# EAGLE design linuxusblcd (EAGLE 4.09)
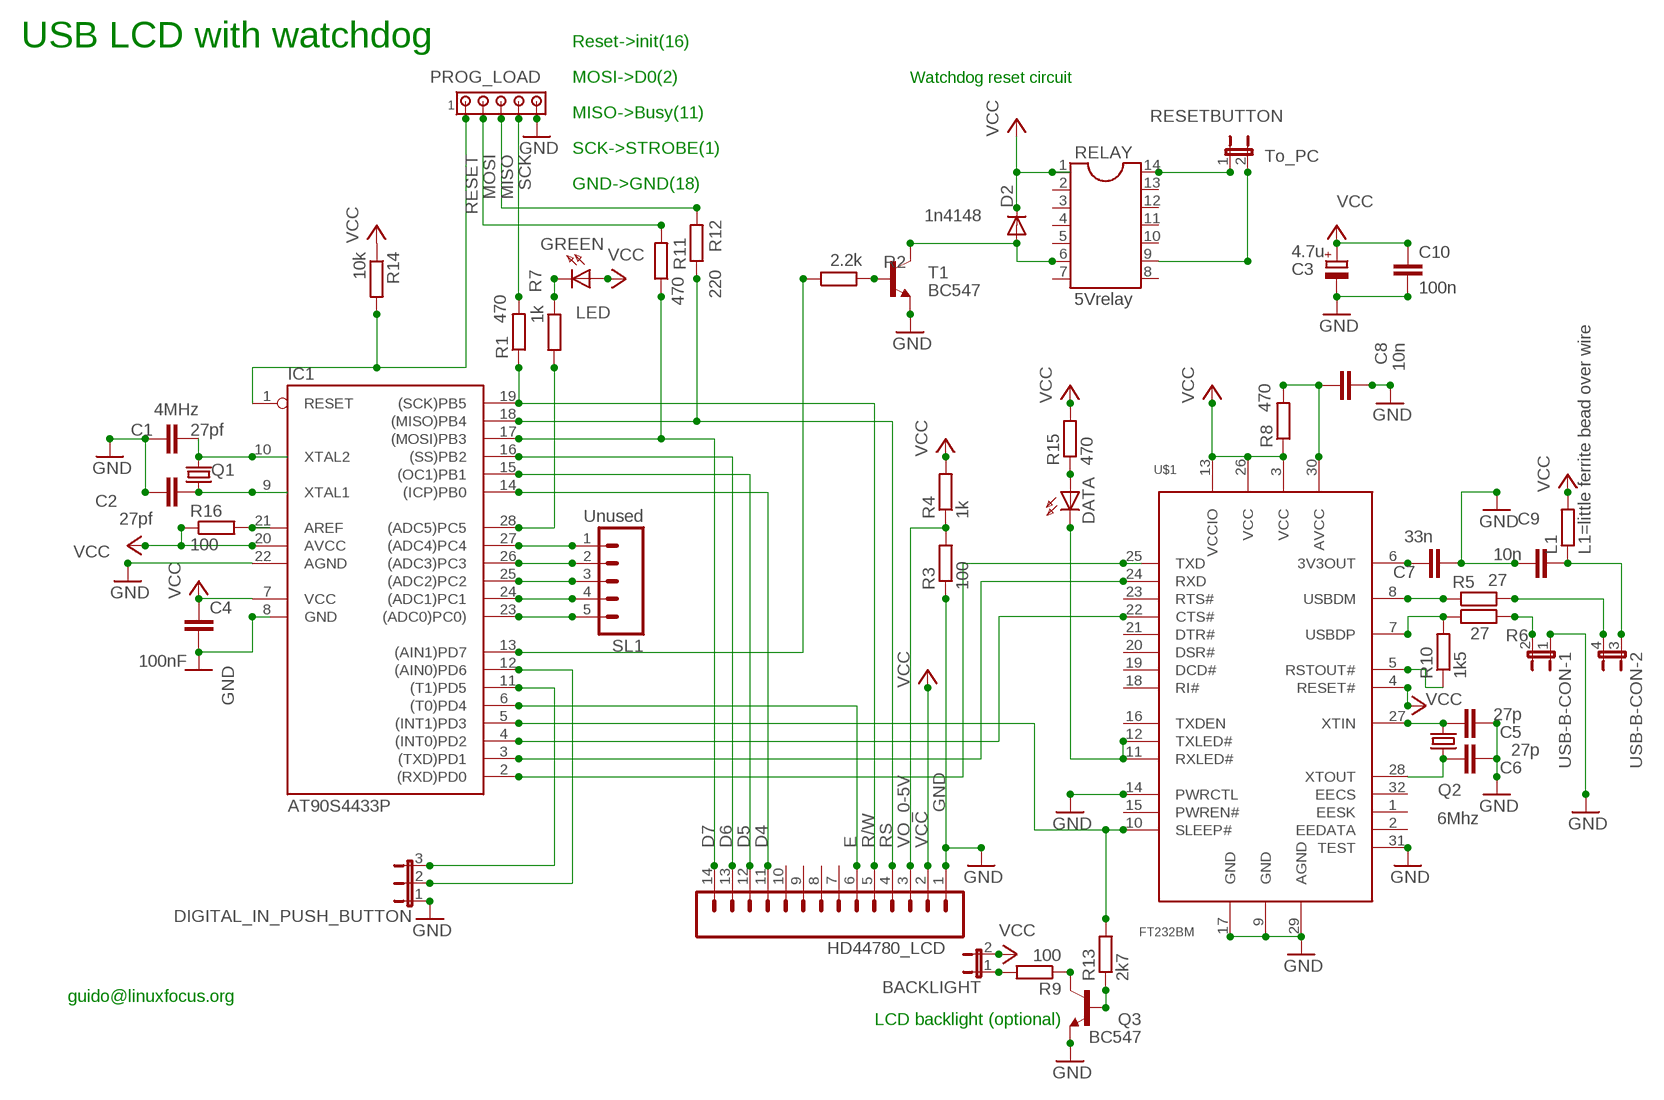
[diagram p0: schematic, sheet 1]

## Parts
BACKLIGHT  JP1E  [JP1]
C1  27pf  C2.5/2  [C2.5-2]
C2  27pf  C2.5/2  [C2.5-2]
C3  4.7u  CPOL-EUE2.5-7  [E2,5-7]
C4  100nF  C-EU025-040X050  [C025-040X050]
C5  27p  C2.5/2  [C2.5-2]
C6  27p  C2.5/2  [C2.5-2]
C7  33n  C-EU050-025X075  [C050-025X075]
C8  10n  C-EU025-030X050  [C025-030X050]
C9  10n  C-EU025-030X050  [C025-030X050]
C10  100n  C-EU025-030X050  [C025-030X050]
D2  1n4148  DIODE-D-5  [D-5]
DATA  LED5MM  [LED5MM]
DIGITAL_IN_PUSH_BUTTON  JP2E  [JP2]
GREEN  LED  LED3MM  [LED3MM]
HD44780_LCD  M14  [14P]
IC1  AT90S4433P  [DIL28-3]
L1  L1=little ferrite bead over wire  R-EU_0204/5  [0204/5]
PROG_LOAD  MTA05-100  [10X05MTA]
Q1  4MHz  HC49U-V  [HC49U-V]
Q2  6Mhz  CRYTALHC49U-V  [HC49U-V]
Q3  BC547  [TO92]
R1  470  R-EU_0204/7  [0204/7]
R2  2.2k  R-EU_0204/5  [0204/5]
R3  100  R-EU_0204/7  [0204/7]
R4  1k  R-EU_0204/7  [0204/7]
R5  27  R-EU_0204/5  [0204/5]
R6  27  R-EU_0204/5  [0204/5]
R7  1k  R-EU_0204/7  [0204/7]
R8  470  R-EU_0204/5  [0204/5]
R9  100  R-EU_0204/7  [0204/7]
R10  1k5  R-EU_0204/5  [0204/5]
R11  470  R-EU_0204/7  [0204/7]
R12  220  R-EU_0204/7  [0204/7]
R13  2k7  R-EU_0204/7  [0204/7]
R14  10k  R-EU_0204/7  [0204/7]
R15  470  R-EU_0204/7  [0204/7]
R16  100  R-EU_0204/7  [0204/7]
RELAY  5Vrelay  DIL14  [DIL14]
RESETBUTTON  To_PC  JP1E  [JP1]
SL1  Unused  M05  [05P]
T1  BC547  [TO92]
U$1  FT232BM  [TQFP32-08]
USB-B-CON  JP2QE  [JP2Q]

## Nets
3V3OUT: C7.1 U$1.6(3V3OUT)
AREF: IC1.21(AREF) R16.2
AVCC: C8.2 R8.2 U$1.30(AVCC)
D4: HD44780_LCD.11 IC1.14((ICP)PB0)
D5: HD44780_LCD.12 IC1.15((OC1)PB1)
D6: HD44780_LCD.13 IC1.16((SS)PB2)
D7: HD44780_LCD.14 IC1.17((MOSI)PB3) R11.1
E: HD44780_LCD.6 IC1.6((T0)PD4)
GND: C1.1 C2.1 C3.- C4.2 C5.2 C6.2 C7.2 C8.1 C9.1 C10.2 DIGITAL_IN_PUSH_BUTTON.1 HD44780_LCD.1 IC1.8(GND) IC1.22(AGND) PROG_LOAD.5 Q3.1(E) R3.1 T1.1(E) U$1.9(GND) U$1.14(PWRCTL) U$1.17(GND) U$1.29(AGND) U$1.31(TEST) USB-B-CON.1
MISO: PROG_LOAD.3 R12.2
MOSI: PROG_LOAD.2 R11.2
N$1: IC1.4((INT0)PD2) U$1.22(CTS#)
N$2: C2.2 IC1.9(XTAL1) Q1.1
N$3: C5.1 Q2.2 U$1.27(XTIN)
N$4: R2.2 T1.2(B)
N$5: IC1.28((ADC5)PC5) R7.2
N$6: DIGITAL_IN_PUSH_BUTTON.3 IC1.11((T1)PD5)
N$7: GREEN.K(C) R7.1
N$8: RELAY.9 RESETBUTTON.2
N$9: RELAY.14 RESETBUTTON.1
N$10: C6.1 Q2.1 U$1.28(XTOUT)
N$11: R5.2 USB-B-CON.4
N$12: R6.2 USB-B-CON.2
N$14: IC1.13((AIN1)PD7) R2.1
N$16: R5.1 U$1.8(USBDM)
N$17: DATA.A R15.1
N$18: IC1.27((ADC4)PC4) SL1.1
N$20: R6.1 R10.2 U$1.7(USBDP)
N$21: DATA.K(C) U$1.11(RXLED#) U$1.12(TXLED#)
N$22: C9.2 L1.1 USB-B-CON.3
N$23: R10.1 U$1.5(RSTOUT#)
N$24: IC1.5((INT1)PD3) R13.2 U$1.10(SLEEP#)
N$25: IC1.26((ADC3)PC3) SL1.2
N$26: IC1.25((ADC2)PC2) SL1.3
N$27: IC1.24((ADC1)PC1) SL1.4
N$28: IC1.23((ADC0)PC0)) SL1.5
N$30: DIGITAL_IN_PUSH_BUTTON.2 IC1.12((AIN0)PD6)
N$31: IC1.3((TXD)PD1) U$1.24(RXD)
N$32: BACKLIGHT.1 R9.2
N$33: Q3.3(C) R9.1
N$34: IC1.2((RXD)PD0) U$1.25(TXD)
N$35: Q3.2(B) R13.1
N$36: C1.2 IC1.10(XTAL2) Q1.2
R/W: HD44780_LCD.5 IC1.19((SCK)PB5) R1.1
RCTL: D2.A RELAY.6 T1.3(C)
RESET: IC1.1(RESET) PROG_LOAD.1 R14.2
RS: HD44780_LCD.4 IC1.18((MISO)PB4) R12.1
SCK: PROG_LOAD.4 R1.2
VCC: BACKLIGHT.2 C3.+ C4.1 C10.1 D2.C GREEN.A HD44780_LCD.2 IC1.7(VCC) IC1.20(AVCC) L1.2 R4.2 R8.1 R14.1 R15.2 R16.1 RELAY.1 U$1.3(VCC) U$1.4(RESET#) U$1.13(VCCIO) U$1.26(VCC)
VO_0-5V: HD44780_LCD.3 R3.2 R4.1
Unconnected: HD44780_LCD.7 HD44780_LCD.8 HD44780_LCD.9 HD44780_LCD.10 RELAY.2 RELAY.3 RELAY.4 RELAY.5 RELAY.7 RELAY.8 RELAY.10 RELAY.11 RELAY.12 RELAY.13 U$1.1(EESK) U$1.2(EEDATA) U$1.15(PWREN#) U$1.16(TXDEN) U$1.18(RI#) U$1.19(DCD#) U$1.20(DSR#) U$1.21(DTR#) U$1.23(RTS#) U$1.32(EECS)

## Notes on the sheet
- USB LCD with watchdog | Reset->init(16)
- MOSI->D0(2) | Watchdog reset circuit
- MISO->Busy(11)
- SCK->STROBE(1)
- GND->GND(18)
- guido@linuxfocus.org
- LCD backlight (optional)

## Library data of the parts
BACKLIGHT RESETBUTTON = jumper:JP1E: JUMPER
C1 C2 C5 C6 = capacitor-wima:C: CAPACITOR
C3 = rcl:CPOL-EU: POLARIZED CAPACITOR, European symbol
C4 C7-C10 = rcl:C-EU: CAPACITOR, European symbol
D2 = diode:DIODE-: DIODE
DATA = led:LED: LED
DIGITAL_IN_PUSH_BUTTON = jumper:JP2E: JUMPER
GREEN = led:LED3MM: LED
HD44780_LCD = con-amp-quick:M14: AMP QUICK CONNECTOR
IC1 = atmel:AT90S4433: MICROCONTROLLER 4 Kbytes FLASH 128 bytes SRAM 256 bytes EEPROM UART 6-channel 10 bit ADC
L1 R1-R3 R5-R16 = rcl:R-EU_: RESISTOR, European symbol
PROG_LOAD = con-amp:MTA05-100: AMP CONNECTOR
Q1 = crystal:HC49U-V: CRYSTAL
Q2 = crystal:CRYTAL: CRYSTAL
Q3 = transistor-npn:BC547*: NPN Transistor
R4 = rcl_gus:R-EU_: RESISTOR, European symbol
RELAY = dil:DIL14: SOCKET Dual In Line
SL1 = con-amp-quick:M05: AMP QUICK CONNECTOR
T1 = transistor-npn:BC547: NPN TRANSISTOR
U$1 = ftdi:FT232BM: USB-Seriell Converter USB 1.1 and USB 2.0
USB-B-CON = jumper:JP2QE: JUMPER

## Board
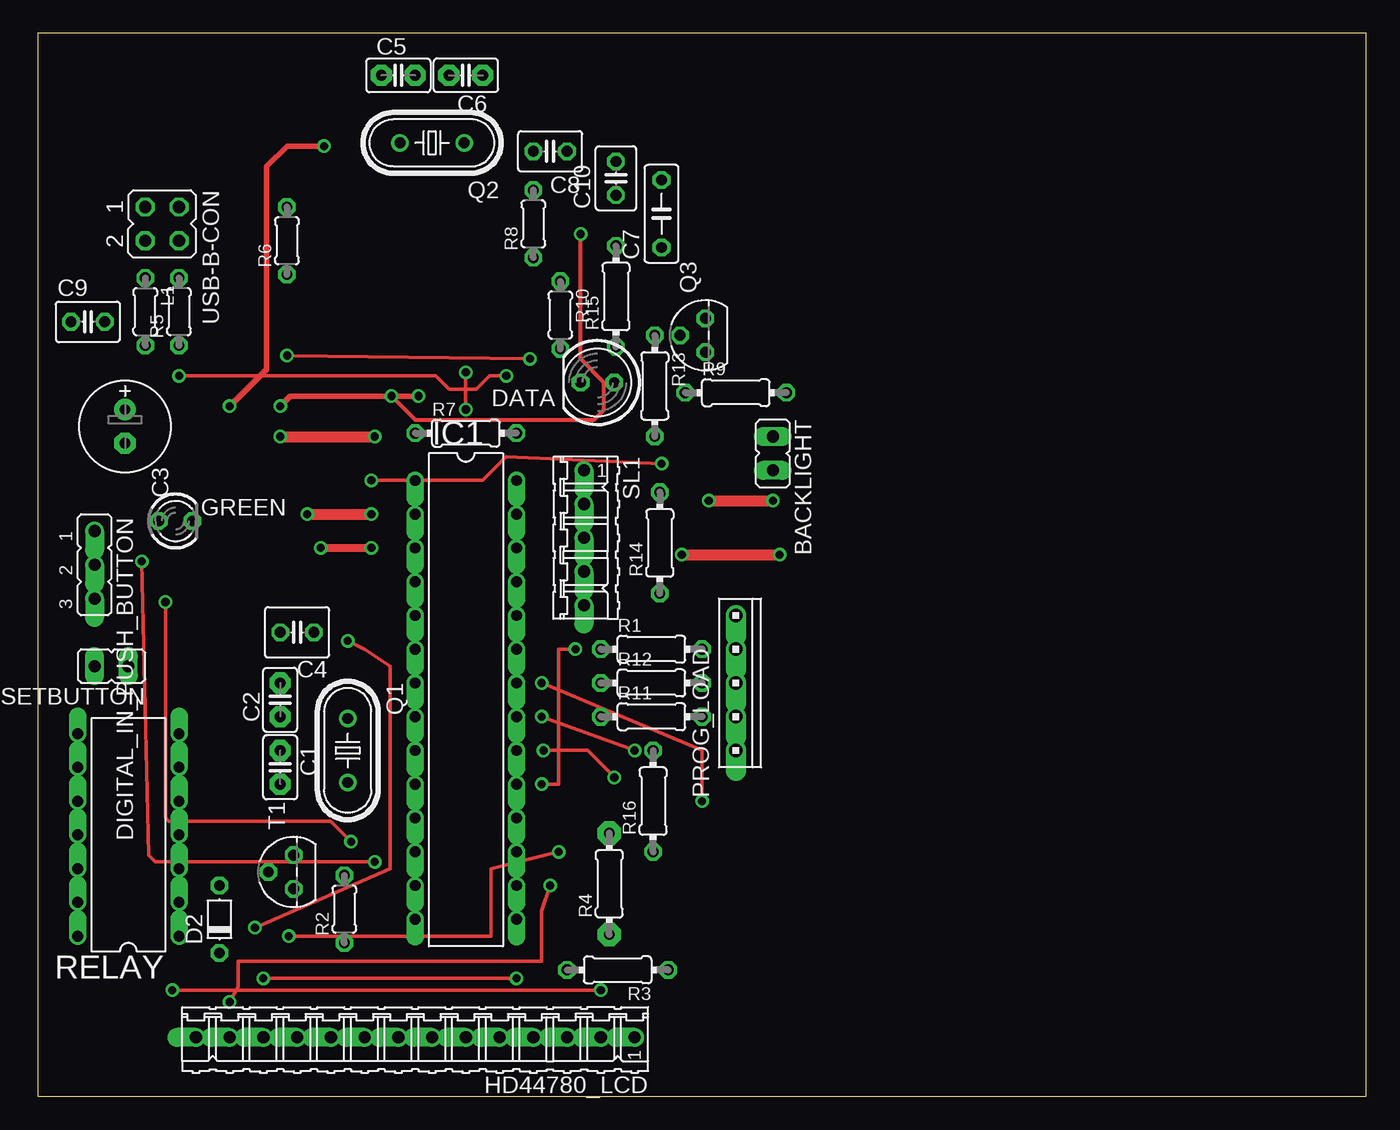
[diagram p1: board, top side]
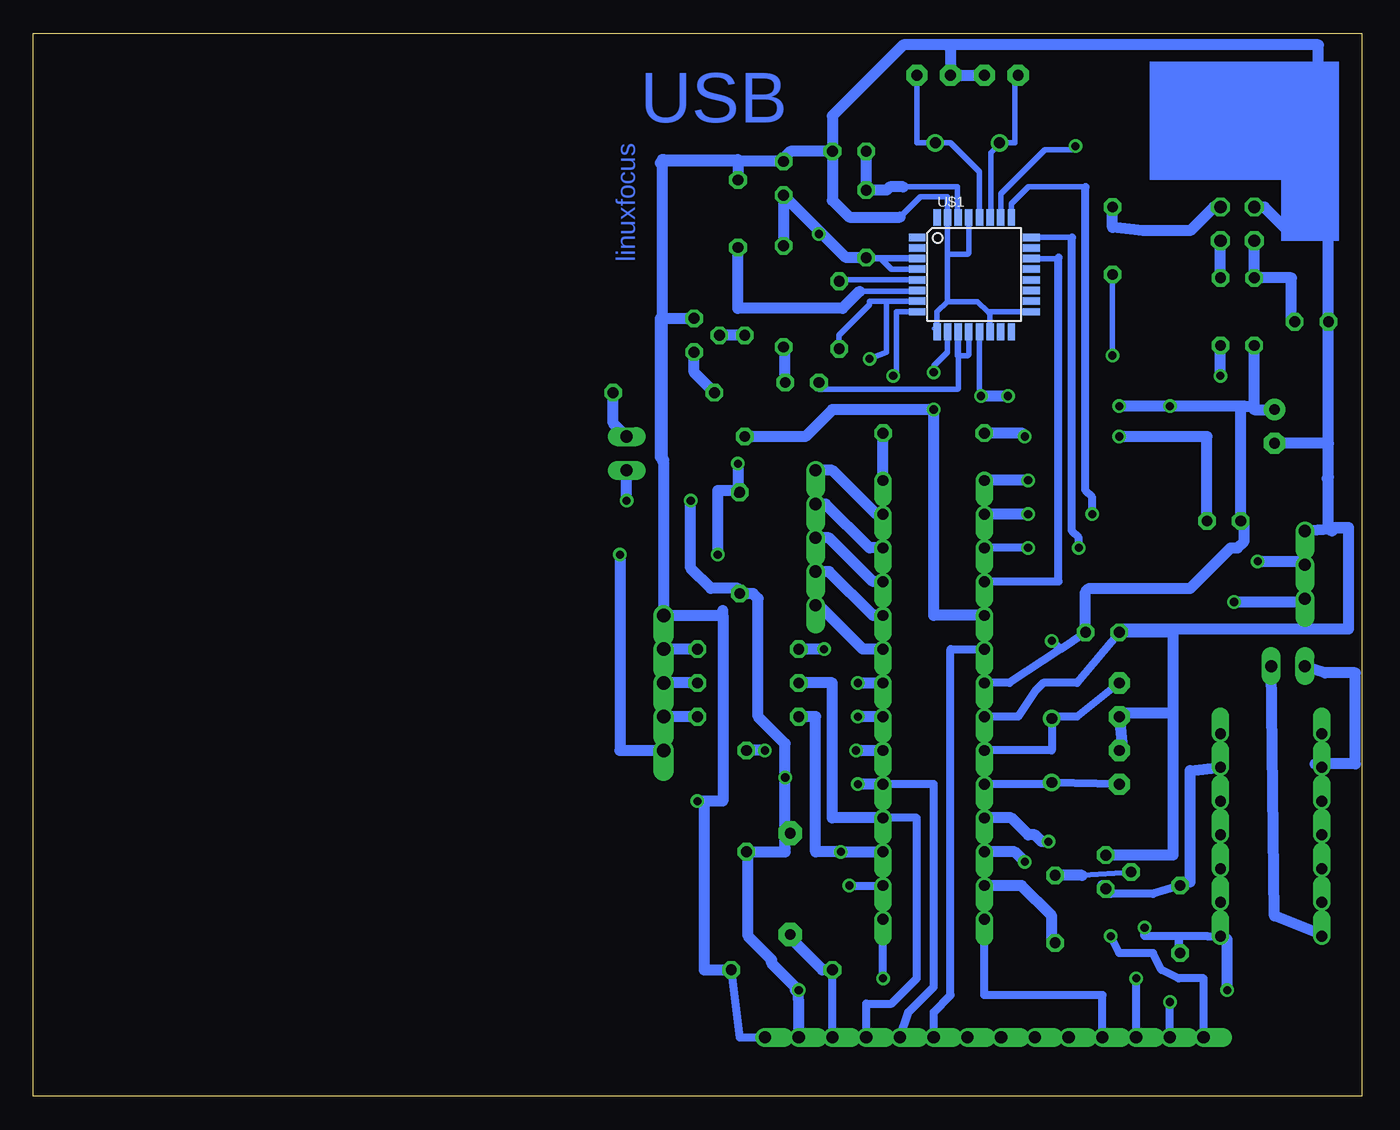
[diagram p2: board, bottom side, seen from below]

Size 100 x 80 mm. Coordinates in mm from the lower left corner, seen from the top.
Outline: 0,0 100,0 100,80 0,80 0,0
Copper layers used: Top, Bottom

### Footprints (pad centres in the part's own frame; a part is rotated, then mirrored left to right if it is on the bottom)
JP1 = drill 0.914 long: 1 0,-1.27; 2 0,1.27
C2.5-2 = drill 0.813 pad 1.6 octagon: 1 -1.27,0; 2 1.27,0
E2,5-7 = drill 0.813 pad 1.6 round: + -1.27,0 | drill 0.813 pad 1.6 octagon: - 1.27,0
C025-040X050 = drill 0.813 octagon: 1 -1.27,0; 2 1.27,0
C050-025X075 = drill 0.813 octagon: 1 -2.54,0; 2 2.54,0
C025-030X050 = drill 0.813 octagon: 1 -1.27,0; 2 1.27,0
D-5 = drill 0.813 octagon: A 2.54,0; C -2.54,0
LED5MM = drill 0.813 octagon: A -1.27,0; K 1.27,0
JP2 = drill 0.914 offset: 1 -2.54,0; 2 0,0; 3 2.54,0
LED3MM = drill 0.813 octagon: A -1.27,0; K 1.27,0
14P = drill 0.914 offset: 1 -16.51,0; 2 -13.97,0; 3 -11.43,0; 4 -8.89,0; 5 -6.35,0; 6 -3.81,0; 7 -1.27,0; 8 1.27,0; 9 3.81,0; 10 6.35,0; 11 8.89,0; 12 11.43,0; 13 13.97,0; 14 16.51,0
DIL28-3 = drill 0.813 offset: 1 -16.51,-3.81; 2 -13.97,-3.81; 3 -11.43,-3.81; 4 -8.89,-3.81; 5 -6.35,-3.81; 6 -3.81,-3.81; 7 -1.27,-3.81; 8 1.27,-3.81; 9 3.81,-3.81; 10 6.35,-3.81; 11 8.89,-3.81; 12 11.43,-3.81; 13 13.97,-3.81; 14 16.51,-3.81; 15 16.51,3.81; 16 13.97,3.81; 17 11.43,3.81; 18 8.89,3.81; 19 6.35,3.81; 20 3.81,3.81; 21 1.27,3.81; 22 -1.27,3.81; 23 -3.81,3.81; 24 -6.35,3.81; 25 -8.89,3.81; 26 -11.43,3.81; 27 -13.97,3.81; 28 -16.51,3.81
0204/5 = drill 0.813 octagon: 1 -2.54,0; 2 2.54,0
10X05MTA = drill 1.016 offset: 1 5.08,0; 2 2.54,0; 3 0,0; 4 -2.54,0; 5 -5.08,0
HC49U-V = drill 0.813 round: 1 -2.413,0; 2 2.413,0
TO92 = drill 0.813 octagon: 1 1.27,0; 2 0,1.905; 3 -1.27,0
0204/7 = drill 0.813 octagon: 1 -3.81,0; 2 3.81,0
0204/7' = drill 0.813 pad 1.778 octagon: 1 -3.81,0; 2 3.81,0
DIL14 = drill 0.813 offset: 1 -7.62,-3.81; 2 -5.08,-3.81; 3 -2.54,-3.81; 4 0,-3.81; 5 2.54,-3.81; 6 5.08,-3.81; 7 7.62,-3.81; 8 7.62,3.81; 9 5.08,3.81; 10 2.54,3.81; 11 0,3.81; 12 -2.54,3.81; 13 -5.08,3.81; 14 -7.62,3.81
05P = drill 0.914 offset: 1 -5.08,0; 2 -2.54,0; 3 0,0; 4 2.54,0; 5 5.08,0
TQFP32-08 = smd 1.27 x 0.559: 1 -4.293,2.8; 2 -4.293,2; 3 -4.293,1.2; 4 -4.293,0.4; 5 -4.293,-0.4; 6 -4.293,-1.2; 7 -4.293,-2; 8 -4.293,-2.8; 17 4.293,-2.8; 18 4.293,-2; 19 4.293,-1.2; 20 4.293,-0.4; 21 4.293,0.4; 22 4.293,1.2; 23 4.293,2; 24 4.293,2.8 | smd 0.559 x 1.27: 9 -2.8,-4.293; 10 -2,-4.293; 11 -1.2,-4.293; 12 -0.4,-4.293; 13 0.4,-4.293; 14 1.2,-4.293; 15 2,-4.293; 16 2.8,-4.293; 25 2.8,4.293; 26 2,4.293; 27 1.2,4.293; 28 0.4,4.293; 29 -0.4,4.293; 30 -1.2,4.293; 31 -2,4.293; 32 -2.8,4.293
JP2Q = drill 0.914 octagon: 1 -1.27,-1.27; 2 -1.27,1.27; 3 1.27,-1.27; 4 1.27,1.27

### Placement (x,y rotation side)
BACKLIGHT  55.33,48.38 180 top
C1  18.25,24.76 270 top
C2  18.25,29.84 90 top
C3  6.57,50.41 270 top
C4  19.52,34.92 180 top
C5  27.14,76.83 0 top
C6  32.22,76.83 180 top
C7  46.95,66.42 90 top
C8  38.57,71.11 180 top
C9  3.77,58.29 0 top
C10  43.52,69.08 90 top
D2  13.68,13.33 90 top
DATA  42.13,53.72 180 top
DIGITAL_IN_PUSH_BUTTON  4.28,40 270 top
GREEN  10.38,43.3 0 top
HD44780_LCD  28.41,4.44 180 top
IC1  32.22,29.84 270 top
L1  8.09,59.05 270 top
PROG_LOAD  52.54,31.11 270 top
Q1  23.33,26.03 270 top
Q2  29.68,71.75 180 top
Q3  50.25,57.27 90 top
R1  46.19,33.65 0 top
R2  23.08,14.09 90 top
R3  43.65,9.52 180 top
R4  1k  [0204/7']  43.02,16 90 top
R5  10.63,59.05 90 top
R6  18.76,64.38 90 top
R7  32.22,49.91 0 top
R8  37.3,65.65 90 top
R9  52.54,52.95 0 top
R10  39.33,58.8 270 top
R11  46.19,28.57 0 top
R12  46.19,31.11 0 top
R13  46.44,53.46 270 top
R14  46.82,41.65 90 top
R15  43.52,60.19 90 top
R16  46.32,22.22 90 top
RELAY  6.82,19.68 90 top
RESETBUTTON  5.55,32.38 90 top
SL1  41.11,42.03 270 top
T1  19.27,16.89 90 top
U$1  29.17,61.84 0 bottom
USB-B-CON  9.36,65.65 270 top

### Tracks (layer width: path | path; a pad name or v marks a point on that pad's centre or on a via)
3V3OUT
  Bottom 0.406: U$1.6 33.46,60.6 33.49,60.57 37.81,60.57
  Bottom 0.813: C7.1 46.95,59.3 39.08,59.3 37.81,60.57
AREF  (via drill 0.61)
  Top 0.254: v37.94,28.57 v44.92,26.03
  Bottom 0.813: IC1.21 v37.94,28.57 | v44.92,26.03 R16.2
AVCC
  Bottom 0.406: 34.51,68.45 30.44,68.45 30.44,66.42 30.37,66.35 U$1.30
  Bottom 0.813: C8.2 R8.2 35.78,68.19 35.52,68.45 34.51,68.45
D4
  Bottom 0.61: IC1.14 28.41,7.62 19.52,7.62 HD44780_LCD.11
D5  (via drill 0.61)
  Top 0.254: v16.98,8.89 v36.03,8.89
  Bottom 0.61: v36.03,8.89 IC1.15 | HD44780_LCD.12 v16.98,8.89
D6  (via drill 0.61)
  Top 0.254: v38.57,15.87 37.94,13.97 37.94,10.16 15.08,10.16 15.08,8.25 v14.44,7.11
  Bottom 0.61: v38.57,15.87 IC1.16 | HD44780_LCD.13 v14.44,7.11
D7  (via drill 0.61)
  Top 0.254: v18.88,12.06 34.12,12.06 34.12,17.14 v39.2,18.41
  Bottom 0.61: HD44780_LCD.14 11.9,8.89 13.81,8.89 15.08,9.52 15.71,10.79 18.25,10.79 v18.88,12.06
  Bottom 0.813: IC1.17 v39.2,18.41 41.11,18.41 41.11,28.57 R11.1
E
  Bottom 0.61: IC1.6 30.95,33.65 30.95,7.62 32.22,6.34 HD44780_LCD.6
GND  (via drill 0.61)
  Top 0.254: v37.94,31.11 50,26.03 v50,22.22
  Bottom 0.305: 18,25.78 C1.1 | U$1.17 25.1,59.04 25.11,59.05 | 31.99,57.55 32.22,57.78 | 31.99,57.55 U$1.9 | 31.97,57.53 31.99,57.55
  Bottom 0.406: U$1.29 29.57,63.48 29.68,63.37 31.2,63.37 31.2,66.16 | 31.2,66.16 U$1.31 31.17,59.84 31.2,59.81 | 31.2,59.81 31.97,59.05 31.97,57.53 | U$1.14 27.97,58.87 28.16,59.05 | 28.16,59.05 25.11,59.05 | 28.16,59.05 28.92,59.81 31.2,59.81 | 31.2,66.16 31.2,67.69 33.24,67.69 34.76,66.16
  Bottom 0.61: IC1.8 25.87,28.57 24.6,30.47 23.96,31.11 21.42,31.11 C4.2 | R3.1 46.82,4.44 HD44780_LCD.1
  Bottom 0.813: C6.2 C5.2 | 0.98,42.79 DIGITAL_IN_PUSH_BUTTON.1 | 0.98,42.79 0.98,35.17 18.25,35.17 C4.2 14.19,34.92 14.19,28.82 | 14.19,28.82 18,28.82 C2.1 18,25.78 | T1.1 14.19,18.16 14.19,28.82 | 52.67,47.87 52.54,47.62 PROG_LOAD.5 48.09,36.19 | 52.67,70.48 52.67,47.87 | 48.09,36.19 48.09,22.22 49.75,22.22 | v37.94,31.11 IC1.22 | 49.75,22.22 v50,22.22 | C1.1 18.5,26.03 | C6.2 30.95,79.12 31.2,79.12 | 31.2,79.12 34.51,79.12 39.84,73.78 39.84,71.24 | 39.84,71.24 C8.1 | C8.1 39.84,70.99 | C8.1 43.02,71.11 43.65,70.48 C10.2 52.41,70.35 52.54,70.48 | 52.54,70.48 52.67,70.48 | 52.54,70.48 46.95,70.48 C7.2 | 3.52,66.92 2.5,66.92 C9.1 2.5,49.14 | 3.52,66.92 3.52,65.4 3.77,65.15 5.55,65.15 7.33,66.92 USB-B-CON.1 | 2.5,46.6 2.5,49.14 | 2.5,42.79 2.5,46.6 | 2.5,42.79 2.25,42.54 | 2.5,49.14 C3.- | 2.5,46.6 2.63,46.48 | C6.2 30.95,78.86 31.2,79.12 | 31.2,79.12 3.26,79.12 3.26,67.18 3.52,66.92 | 48.09,36.19 48.09,36.57 | R3.1 49.49,9.52 49.49,21.97 49.75,22.22 | 34.76,66.16 38.57,66.16 39.84,67.43 39.84,71.24 | 52.54,70.48 52.67,70.35 | 52.67,70.48 52.67,70.35 | 52.67,70.35 52.79,70.23 | 0.98,42.79 2.5,42.79 | Q3.1 52.79,58.54 52.79,48.13 52.54,47.87 52.67,47.87
MISO
  Bottom 0.813: R12.2 PROG_LOAD.3
MOSI
  Bottom 0.813: R11.2 PROG_LOAD.2
N$1
  Bottom 0.406: U$1.22 22.89,63.04 22.82,63.11
  Bottom 0.61: 22.82,63.11 22.82,38.73 IC1.4
N$2
  Bottom 0.61: IC1.9 23.33,26.03 Q1.1 23.33,28.57 21.42,28.57 C2.2
N$3
  Bottom 0.406: U$1.27 27.9,66.14 27.9,70.99 27.14,71.75 Q2.2 26.12,71.75 26.12,76.58 C5.1
N$4
  Bottom 0.406: T1.2 21.04,16.63
  Bottom 0.813: 21.04,16.63 R2.2
N$5
  Bottom 0.813: IC1.28 R7.2
N$6  (via drill 0.61)
  Top 0.254: v9.61,37.21 9.61,20.95 9.87,20.7 22.06,20.7 v23.58,19.17
  Bottom 0.813: DIGITAL_IN_PUSH_BUTTON.3 4.28,37.21 v9.61,37.21 | v23.58,19.17 24.09,19.17 24.6,19.68 25.11,19.68 26.38,20.95 IC1.11 28.66,20.95
N$7  (via drill 0.61)
  Top 0.813: v18.25,49.65 v25.36,49.65
  Bottom 0.813: R7.1 25.62,49.91 v25.36,49.65 | v18.25,49.65 11.65,49.65 GREEN.K
N$8
  Bottom 0.305: 3.52,25.01 RELAY.9
  Bottom 0.813: RESETBUTTON.2 2.76,31.87 0.47,31.87 0.47,25.01 3.52,25.01
N$9
  Bottom 0.813: RESETBUTTON.1 6.57,13.58 2.76,12.06 RELAY.14
N$10
  Bottom 0.406: U$1.28 28.77,69.57 30.95,71.75 Q2.1 33.49,71.75 C6.1
N$11
  Bottom 0.813: R5.2 USB-B-CON.4
N$12
  Bottom 0.813: USB-B-CON.2 11.14,66.92 12.92,65.15 16.47,65.15 18.76,65.4 R6.2
N$14
  Bottom 0.813: IC1.13 25.62,15.87 23.33,13.58 23.33,11.55 R2.1
N$16  (via drill 0.61)
  Top 0.254: v10.63,54.22 29.93,54.22 30.95,53.21 32.98,53.21 34,54.22 v35.27,54.22 35.52,54.22
  Bottom 0.406: U$1.8 35.01,59.04 35.01,59.05 35.01,54.48 v35.27,54.22
  Bottom 0.813: v10.63,54.22 R5.1
N$17
  Bottom 0.813: R15.1 43.4,56.38 DATA.A
N$18
  Bottom 0.813: IC1.27 36.54,43.81 39.84,47.11 SL1.1
N$20  (via drill 0.61)
  Top 0.254: v18.76,55.75 v37.05,55.49
  Bottom 0.406: R10.2 39.59,56.26 39.33,56.51 39.33,57.27 37.05,59.56 37.05,59.81 37.01,59.84 U$1.7 35.74,59.84 35.78,59.81 35.78,56 v37.05,55.49 | v18.76,55.75 R6.1
N$21
  Bottom 0.406: U$1.12 29.57,55.86 29.68,55.75 30.44,55.75 30.44,57.27 30.37,57.34 U$1.11 30.37,53.28 30.44,53.21 40.86,53.21 DATA.K
N$22
  Bottom 0.813: USB-B-CON.3 L1.1 5.3,61.59 5.3,58.54 C9.2
N$23
  Bottom 0.406: U$1.5 39.22,61.44 R10.1
N$24  (via drill 0.61)
  Top 0.254: v32.22,51.68 v32.22,54.48
  Bottom 0.406: v32.22,54.48 32.22,54.99 31.2,56 31.2,57.27 31.17,57.3 U$1.10
  Bottom 0.813: IC1.5 32.22,36.19 v32.22,51.68 39.84,51.68 41.87,49.65 R13.2
N$25
  Bottom 0.813: IC1.26 37.05,41.27 40.35,44.57 SL1.2
N$26
  Bottom 0.813: IC1.25 36.79,38.73 40.09,42.03 SL1.3 41.36,42.03
N$27
  Bottom 0.813: IC1.24 36.79,36.19 40.09,39.49 SL1.4
N$28
  Bottom 0.813: SL1.5 41.11,37.21 37.55,33.65 IC1.23
N$30  (via drill 0.61)
  Top 0.254: v25.36,17.65 8.85,17.65 8.34,18.16 v7.84,40.25
  Bottom 0.813: IC1.12 26.12,18.41 v25.36,17.65 | v7.84,40.25 4.53,40.25 DIGITAL_IN_PUSH_BUTTON.2
N$31  (via drill 0.61)
  Top 0.61: v21.3,41.27 v25.11,41.27
  Bottom 0.406: U$1.24 21.81,64.64
  Bottom 0.61: v21.3,41.27 21.3,42.03 21.81,42.54 21.81,64.64 | v25.11,41.27 IC1.3
N$32
  Bottom 0.813: R9.2 56.35,50.67 BACKLIGHT.1
N$33
  Bottom 0.813: Q3.3 50.25,54.48 R9.1
N$34  (via drill 0.61)
  Top 0.813: v20.28,43.81 v25.11,43.81
  Bottom 0.406: U$1.25 26.37,67.18 25.11,68.45 20.79,68.45
  Bottom 0.61: v20.28,43.81 20.28,45.08 20.79,45.59 20.79,68.45
  Bottom 0.813: v25.11,43.81 IC1.2
N$35
  Bottom 0.813: R13.1 Q3.2
N$36
  Bottom 0.61: IC1.10 23.33,23.49 Q1.2 C1.2
R/W  (via drill 0.61)
  Top 0.254: v40.48,33.65 39.2,33.65 39.2,23.49 v37.94,23.49
  Bottom 0.61: HD44780_LCD.5 34.12,6.34 32.22,8.25 32.22,23.49 IC1.19
  Bottom 0.813: v40.48,33.65 R1.1 | IC1.19 v37.94,23.49
RCTL
  Bottom 0.61: D2.A 13.81,15.87 | 12.92,16.12 D2.A | D2.A 15.71,15.24 18.88,15.24 19.52,15.87
  Bottom 0.813: RELAY.6 12.92,24.51 12.92,16.12 | 19.52,15.87 T1.3
RESET  (via drill 0.61)
  Top 0.254: v25.11,46.35 33.49,46.35 35.27,48.13 v46.95,47.62
  Top 0.813: v48.48,40.76 v55.84,40.76 | v46.95,45.33 R14.2
  Bottom 0.813: 47.21,45.59 48.48,45.59 v48.48,40.76 | 47.21,45.59 46.95,45.59 | PROG_LOAD.1 55.84,26.03 v55.84,40.76 | v25.11,46.35 IC1.1 | 47.21,45.59 v46.95,45.33 | v46.95,47.62 46.95,45.84 47.21,45.59
RS
  Bottom 0.61: IC1.18 33.49,20.95 33.49,8.89 35.39,6.98 37.3,6.98 HD44780_LCD.4
  Bottom 0.813: IC1.18 39.84,20.95 39.84,31.11 R12.1
SCK
  Bottom 0.813: R1.2 PROG_LOAD.4
VCC  (via drill 0.61)
  Top 0.254: v16.34,12.7 26.5,17.14 26.5,32.38 24.6,33.65 v23.33,34.29 | v10.12,8 v42.38,8 | v38.06,26.03 41.36,26.03 v43.4,24
  Top 0.305: v40.86,64.89 40.86,55.49 42.63,53.72 42.63,51.68 41.87,50.92 28.41,50.92 v26.63,52.7
  Top 0.406: v21.55,71.5 18.76,71.5 17.23,69.97 17.23,54.73 v14.44,51.94 | v28.66,52.7 v26.63,52.7 19.01,52.7 v18.25,51.94
  Top 0.813: v50.51,44.83 v55.33,44.83
  Bottom 0.305: U$1.3 39.01,63.04 v40.86,64.89 | R16.1 46.32,18.54 46.44,18.66 46.44,18.41 | v42.38,8 42.38,7.23 | 10.38,12.06 11.65,12.06
  Bottom 0.406: 36.28,63.11 R8.1 37.23,63.04 U$1.3 33.67,63.04 33.74,63.11 36.28,63.11 | U$1.4 35.41,62.24 36.28,63.11 | U$1.26 27.17,67.91 23.84,71.24 21.81,71.24 v21.55,71.5 | U$1.13 28.77,52.81 v28.66,52.7
  Bottom 0.61: IC1.7 26.5,31.11 22.7,33.65 | 22.7,33.65 C4.1 | v23.33,34.29 22.7,33.65 | RELAY.1 11.65,12.06 13.81,12.06 | 13.81,12.06 13.81,10.79 D2.C 13.81,12.06 | 13.81,12.06 16.34,12.06 v16.34,12.7
  Bottom 0.813: R8.1 38.82,63.11 C10.1 R15.2 43.4,63.88 | 8.09,51.94 L1.2 | 6.31,51.68 C3.+ 8.09,51.68 8.09,51.94 | v42.38,8 44.41,10.03 44.41,10.28 46.19,12.06 46.19,18.16 46.44,18.41 R16.1 43.65,18.41 | 43.65,18.41 43.4,18.41 43.4,19.93 43.27,19.81 R4.2 | 8.85,51.94 9.11,51.68 GREEN.A 8.85,43.05 8.85,41.78 9.36,41.27 9.87,41.27 12.92,38.22 20.54,38.22 20.79,37.97 C4.1 | 8.85,51.94 8.09,51.94 | 8.85,51.94 v14.44,51.94 v18.25,51.94 | v10.12,8 10.12,11.81 10.38,12.06 | HD44780_LCD.2 42.38,7.23 42.38,7.74 42.63,8 | v38.06,26.03 IC1.20 | 43.65,18.41 43.4,18.66 v43.4,24 43.4,26.54 45.43,28.57 45.43,37.46 45.81,37.84 R14.1 46.95,37.71 46.95,38.22 48.98,38.22 50.51,39.75 v50.51,44.83 | v26.63,52.7 v28.66,52.7 | v55.33,44.83 BACKLIGHT.2
VO_0-5V
  Bottom 0.61: HD44780_LCD.3 R3.2
  Bottom 0.813: 43.27,12.19 43.4,12.31 | 43.27,12.19 R4.1 | R3.2 40.6,9.52 43.27,12.19
(copper drawn outside any net)
  shapes: Bottom area x3

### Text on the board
Bottom: USB | linuxfocus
